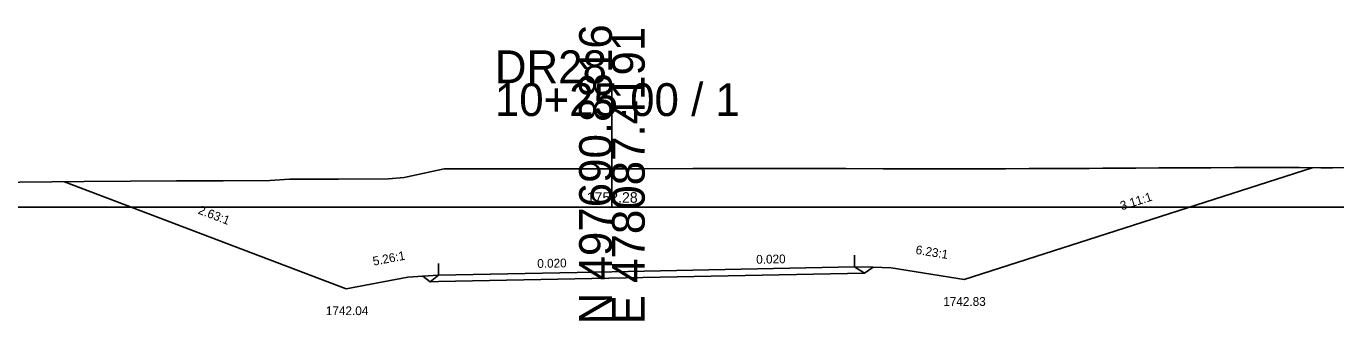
# Model space of a CAD drawing. Extents: x -26 to 303, y -10 to 3689.
# Drawn here: x 100 to 211.8, y 490.3 to 515.4 of the extents above; entities that cross this region are included whole.
import ezdxf

# ---------------------------------------------------------------- set-up
doc = ezdxf.new("R2010")
doc.units = 0
for name, color, linetype in [('Exist Cross Section Cell', 7, 'Continuous'), ('Exist XS Center Line Elevation Label', 7, 'Continuous'), ('Exist XS Ground Line', 7, 'Continuous'), ('Prop XS Ditch Slope Text', 7, 'Continuous'), ('Prop XS Ditch Standard Text', 7, 'Continuous'), ('Prop XS Dump Level', 7, 'Continuous'), ('Prop XS Earthwork Shape', 7, 'Continuous'), ('Prop XS EOT Tick Mark', 7, 'Continuous'), ('Prop XS Finish Grade', 7, 'Continuous'), ('Prop XS Finish Grade Earthwork', 7, 'Continuous'), ('Prop XS Finish Grade Pavement', 7, 'Continuous'), ('Prop XS Hydro Typical Ditch Data', 7, 'Continuous'), ('Prop XS Pvmt Edge Slope', 7, 'Continuous'), ('Prop XS SE Text', 7, 'Continuous'), ('Prop XS Shoulder Borrow Shape', 7, 'Continuous'), ('Prop XS Side Slope Text', 7, 'Continuous'), ('Prop XS Subgrade Earthwork', 7, 'Continuous')]:
    doc.layers.add(name, color=color, linetype=linetype)

msp = doc.modelspace()

# ---------------------------------------------------------------- linework, layer by layer
at = {"layer": 'Exist Cross Section Cell'}
for p, q in [((150, 500), (150, 510.58)), ((0, 500), (150, 500)), ((150, 500), (300, 500))]:
    msp.add_line(p, q, dxfattribs=at)
at = {"layer": 'Exist XS Ground Line'}
msp.add_lwpolyline([(96.65, 502.12), (104.94, 502.18), (108.87, 502.21), (112.82, 502.24), (116.8, 502.26), (120.79, 502.28), (122.45, 502.38), (126.65, 502.4), (130.93, 502.42), (132.27, 502.54), (135.67, 503.26), (139.8, 503.27), (144.02, 503.27), (148.33, 503.28), (150, 503.28), (152.72, 503.28), (156.91, 503.29), (161.24, 503.3), (165.66, 503.3), (169.99, 503.3), (173.17, 503.28), (176.92, 503.28), (180.41, 503.28), (183.62, 503.28), (185.64, 503.31), (188.36, 503.31), (190.77, 503.31), (191.93, 503.32), (194.75, 503.34), (196.71, 503.37), (197.32, 503.37), (198.09, 503.37), (199.26, 503.37), (201.15, 503.37), (203.16, 503.38), (203.63, 503.38), (203.98, 503.38), (206.18, 503.39), (206.63, 503.39), (208.72, 503.38), (210.55, 503.37), (211.53, 503.37), (213.19, 503.38)], dxfattribs=at)
at = {"layer": 'Prop XS Dump Level'}
for p in [(135.2, 494.2), (170.73, 494.91)]:
    msp.add_line(p, (150, 494.49), dxfattribs=at)
at = {"layer": 'Prop XS Earthwork Shape'}
msp.add_lwpolyline([(206.18, 503.39), (206.63, 503.39), (208.72, 503.38), (209.79, 503.37), (180.07, 493.83), (173.84, 494.83), (172.32, 494.87), (171.56, 494.38), (135.2, 493.66), (134.47, 493.64), (133.85, 494.12), (132.57, 494.04), (127.3, 493.04), (103.26, 502.17), (104.94, 502.18), (108.87, 502.21), (112.82, 502.24), (116.8, 502.26), (120.79, 502.28), (122.45, 502.38), (126.65, 502.4), (130.93, 502.42), (132.27, 502.54), (135.67, 503.26), (139.8, 503.27), (144.02, 503.27), (148.33, 503.28), (150, 503.28), (152.72, 503.28), (156.91, 503.29), (161.24, 503.3), (165.66, 503.3), (169.99, 503.3), (173.17, 503.28), (176.92, 503.28), (180.41, 503.28), (183.62, 503.28), (185.64, 503.31), (188.36, 503.31), (190.77, 503.31), (191.93, 503.32), (194.75, 503.34), (196.71, 503.37), (197.32, 503.37), (198.09, 503.37), (199.26, 503.37), (201.15, 503.37), (203.16, 503.38), (203.63, 503.38), (203.98, 503.38)], close=True, dxfattribs=at)
msp.add_lwpolyline([(206.18, 503.39), (206.63, 503.39), (208.72, 503.38), (209.79, 503.37), (180.07, 493.83), (173.84, 494.83), (172.32, 494.87), (171.56, 494.38), (135.2, 493.66), (134.47, 493.64), (133.85, 494.12), (132.57, 494.04), (127.3, 493.04), (103.26, 502.17), (104.94, 502.18), (108.87, 502.21), (112.82, 502.24), (116.8, 502.26), (120.79, 502.28), (122.45, 502.38), (126.65, 502.4), (130.93, 502.42), (132.27, 502.54), (135.67, 503.26), (139.8, 503.27), (144.02, 503.27), (148.33, 503.28), (150, 503.28), (152.72, 503.28), (156.91, 503.29), (161.24, 503.3), (165.66, 503.3), (169.99, 503.3), (173.17, 503.28), (176.92, 503.28), (180.41, 503.28), (183.62, 503.28), (185.64, 503.31), (188.36, 503.31), (190.77, 503.31), (191.93, 503.32), (194.75, 503.34), (196.71, 503.37), (197.32, 503.37), (198.09, 503.37), (199.26, 503.37), (201.15, 503.37), (203.16, 503.38), (203.63, 503.38), (203.98, 503.38)], close=True, dxfattribs=at)
at = {"layer": 'Prop XS EOT Tick Mark'}
for p, q in [((170.73, 494.91), (170.73, 495.91)), ((135.2, 494.2), (135.2, 495.2))]:
    msp.add_line(p, q, dxfattribs=at)
at = {"layer": 'Prop XS Finish Grade'}
for p, q in [((170.73, 494.91), (172.32, 494.87)), ((135.2, 494.2), (133.85, 494.12))]:
    msp.add_line(p, q, dxfattribs=at)
at = {"layer": 'Prop XS Finish Grade Earthwork'}
for p, q in [((180.07, 493.83), (209.79, 503.37)), ((127.3, 493.04), (103.26, 502.17)), ((172.32, 494.87), (173.84, 494.83)), ((173.84, 494.83), (180.07, 493.83)), ((132.57, 494.04), (127.3, 493.04)), ((133.85, 494.12), (132.57, 494.04))]:
    msp.add_line(p, q, dxfattribs=at)
at = {"layer": 'Prop XS Finish Grade Pavement'}
for p, q in [((135.2, 494.2), (150, 494.49)), ((150, 494.49), (170.73, 494.91))]:
    msp.add_line(p, q, dxfattribs=at)
at = {"layer": 'Prop XS Hydro Typical Ditch Data'}
for p, q in [((127.3, 493.04), (103.26, 502.17)), ((132.57, 494.04), (127.3, 493.04))]:
    msp.add_line(p, q, dxfattribs=at)
at = {"layer": 'Prop XS Pvmt Edge Slope'}
for p, q in [((170.73, 494.91), (171.56, 494.38)), ((135.2, 494.2), (134.47, 493.64))]:
    msp.add_line(p, q, dxfattribs=at)
at = {"layer": 'Prop XS Shoulder Borrow Shape'}
for points in [[(171.56, 494.38), (172.32, 494.87), (170.73, 494.91)], [(135.2, 494.2), (134.47, 493.64), (133.85, 494.12)]]:
    msp.add_lwpolyline(points, close=True, dxfattribs=at)
at = {"layer": 'Prop XS Subgrade Earthwork'}
for p, q in [((171.56, 494.38), (135.2, 493.66)), ((171.56, 494.38), (172.32, 494.87)), ((134.47, 493.64), (133.85, 494.12)), ((135.2, 493.66), (134.47, 493.64))]:
    msp.add_line(p, q, dxfattribs=at)

# ---------------------------------------------------------------- texts
at = {"layer": 'Exist Cross Section Cell'}
for s, p in [('N 497690.8816', (150, 490)), ('E 478087.4191', (152.8, 490))]:
    msp.add_text(s, height=2.8, rotation=90, dxfattribs=at).set_placement(p)
for s, p in [('DR28', (140, 510.58)), ('10+25.00 / 1', (140, 507.78))]:
    msp.add_text(s, height=2.8, dxfattribs=at).set_placement(p)
at = {"layer": 'Exist XS Center Line Elevation Label'}
msp.add_text('1752.28', height=0.9, dxfattribs=at).set_placement((147.85, 500.38))
at = {"layer": 'Prop XS Ditch Slope Text'}
for s, rotation, p in [('6.23:1', 350.8774, (175.9, 496.02)), ('5.26:1', 10.7563, (129.65, 495.01))]:
    msp.add_text(s, height=0.75, rotation=rotation, dxfattribs=at).set_placement(p)
at = {"layer": 'Prop XS Ditch Standard Text'}
for s, p in [('1742.83', (178.3, 491.58)), ('1742.04', (125.57, 490.79))]:
    msp.add_text(s, height=0.75, dxfattribs=at).set_placement(p)
at = {"layer": 'Prop XS Dump Level'}
for p in [(173.84, 494.79), (132.57, 494)]:
    msp.add_text('Case1', height=0.04, dxfattribs=at).set_placement(p)
at = {"layer": 'Prop XS SE Text'}
for p in [(143.63, 494.82), (162.33, 495.17)]:
    msp.add_text('0.020', height=0.75, rotation=1.1458, dxfattribs=at).set_placement(p)
at = {"layer": 'Prop XS Side Slope Text'}
for s, rotation, p in [('3.11:1', 17.8048, (193.55, 499.73)), ('2.63:1', 339.1962, (114.59, 499.47))]:
    msp.add_text(s, height=0.75, rotation=rotation, dxfattribs=at).set_placement(p)

doc.saveas('drawing.dxf')
